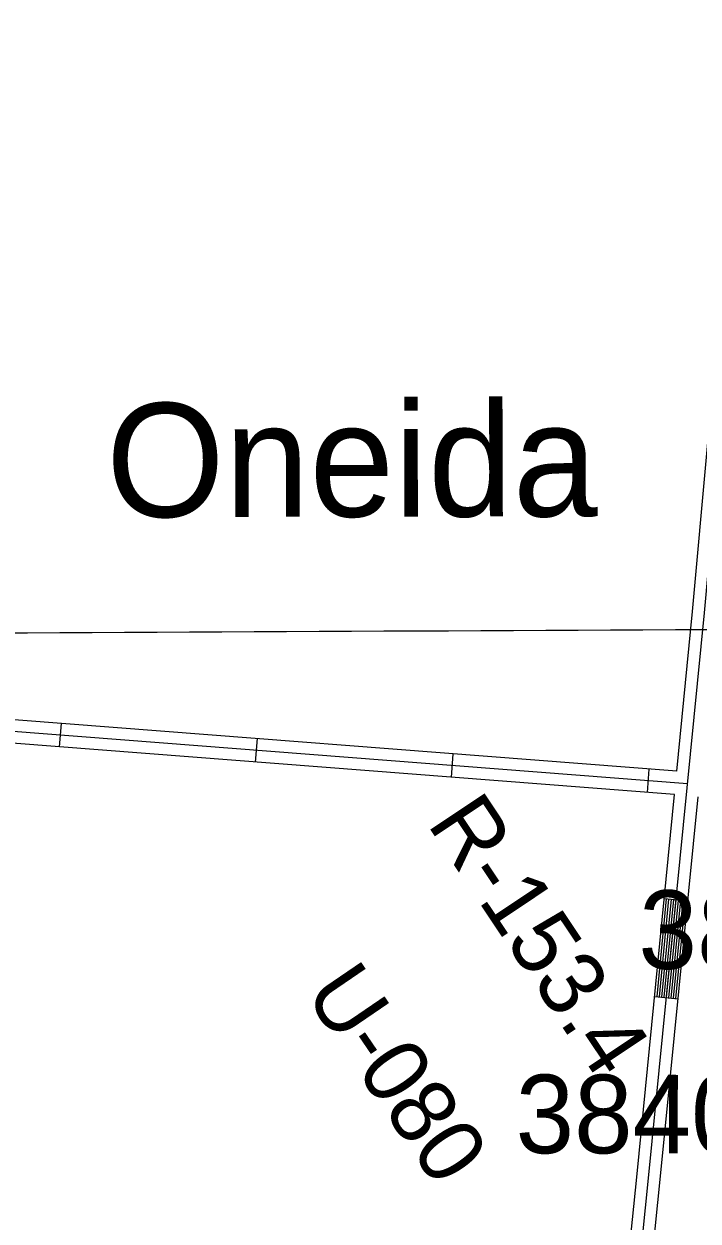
# Model space of a CAD drawing. Extents: x 3419139 to 3457078, y 540382 to 565875.
# Drawn here: x 3452584 to 3453441, y 551211 to 552735 of the extents above; entities that cross this region are included whole.
import ezdxf

# ---------------------------------------------------------------- set-up
doc = ezdxf.new("R2010")
doc.units = 0
for name, color, linetype in [('V-GRID-MAJR', 7, 'Continuous'), ('V-RIVR-RANG-IDEN', 7, 'Continuous'), ('V-ROAD-CNTR', 7, 'Continuous'), ('V-SURV-IDEN', 7, 'Continuous'), ('V-TOPO-GNAM-IDEN', 7, 'Continuous')]:
    doc.layers.add(name, color=color, linetype=linetype)

msp = doc.modelspace()

# ---------------------------------------------------------------- linework, layer by layer
at = {"layer": 'V-GRID-MAJR'}
msp.add_spline([(3423248.5, 551833.1), (3428523.1, 551854.2), (3433797.7, 551876), (3439072.3, 551898.7), (3444346.9, 551922.1), (3449621.5, 551946.2), (3454896.1, 551971.2)], degree=3, dxfattribs=at)
at = {"layer": 'V-ROAD-CNTR'}
for p, q in [((3452629.3, 551814.9), (3452631.6, 551844.8)), ((3452878.5, 551795.5), (3452880.9, 551825.4)), ((3453127.8, 551776.1), (3453130.1, 551806)), ((3453377, 551756.8), (3453379.4, 551786.7)), ((3453398.6, 551621.8), (3453428.4, 551618.8)), ((3453386.3, 551497.4), (3453416.1, 551494.4))]:
    msp.add_line(p, q, dxfattribs=at)
for points in [[(3453343.2, 550823.7), (3453344.4, 550930), (3453379, 551270.2), (3453449.5, 551985.5), (3453525.2, 552823.2), (3453567.1, 553344.9), (3453572.2, 553383.2), (3453581, 553413.4), (3453591.7, 553439.5), (3453616, 553481.4), (3453658.6, 553543.1), (3453688, 553594.5), (3453720.1, 553656.5), (3453724.1, 553674.2), (3453736, 553771.9), (3453793.6, 554410.9), (3453851.2, 555091.5), (3453909.6, 555747.5), (3453945.8, 556130), (3453974.9, 556467.7), (3454011.8, 556908.2), (3454080.8, 557648.6)], [(3453414.6, 551783.9), (3453434.6, 551987), (3453510.3, 552824.4), (3453552.2, 553346.5), (3453557.5, 553386.3), (3453566.9, 553418.3), (3453578.2, 553446.2), (3453603.3, 553489.5), (3453645.9, 553551.1), (3453674.9, 553601.7), (3453691.9, 553634.6)], [(3453414.6, 551783.9), (3452516.4, 551853.7), (3451811.9, 551908.2), (3451307.4, 551947.9), (3451008.7, 551971.6), (3451005.3, 551972.3), (3451001.2, 551973.2), (3450997.1, 551974.3), (3450992.9, 551975.3), (3450988.8, 551976.5), (3450984.7, 551977.7), (3450980.6, 551979), (3450976.6, 551980.3), (3450972.6, 551981.7), (3450968.6, 551983.2), (3450964.7, 551984.8), (3450960.8, 551986.4)], [(3453411.6, 551754.1), (3452514, 551823.8), (3451809.6, 551878.3), (3451305, 551918), (3451004.6, 551941.9), (3450999.1, 551943), (3450994.4, 551944), (3450989.8, 551945.1), (3450985.1, 551946.3), (3450980.5, 551947.6), (3450976, 551949), (3450971.4, 551950.4), (3450966.8, 551952), (3450962.3, 551953.6), (3450957.6, 551955.3)], [(3453428, 551767.8), (3452515.2, 551838.8), (3451810.7, 551893.2), (3451306.2, 551933), (3451006.7, 551956.7)], [(3453328.2, 550823.9), (3453329.4, 550930.9), (3453364, 551271.7), (3453411.6, 551754.1)], [(3453358.2, 550823.6), (3453359.4, 550929.2), (3453393.9, 551268.7), (3453441.5, 551751.2)], [(3453389.3, 551497.1), (3453401.5, 551621.5)], [(3453392.3, 551496.8), (3453404.5, 551621.2)], [(3453395.2, 551496.5), (3453407.5, 551620.9)], [(3453398.2, 551496.2), (3453410.5, 551620.6)], [(3453401.2, 551495.9), (3453413.5, 551620.3)], [(3453404.2, 551495.6), (3453416.5, 551620)], [(3453407.2, 551495.3), (3453419.5, 551619.7)], [(3453410.2, 551495), (3453422.4, 551619.4)], [(3453413.2, 551494.7), (3453425.4, 551619.1)]]:
    msp.add_lwpolyline(points, dxfattribs=at)

# ---------------------------------------------------------------- texts
at = {"layer": 'V-RIVR-RANG-IDEN'}
for s, rotation, p in [('R-153.4', 303.7342, (3453095.8, 551717.2)), ('U-080', 304.3105, (3452939.5, 551501.3))]:
    msp.add_text(s, height=83, rotation=rotation, dxfattribs=at).set_placement(p)
at = {"layer": 'V-SURV-IDEN'}
for s, rotation, p in [('3842+88.4', 358.9715, (3453365.2, 551533)), ('3840+18.0', 359.9301, (3453209.4, 551297.8))]:
    msp.add_text(s, height=100, rotation=rotation, dxfattribs=at).set_placement(p)
at = {"layer": 'V-TOPO-GNAM-IDEN'}
msp.add_text('Oneida', height=145, rotation=0.088, dxfattribs=at).set_placement((3452688.6, 552107.3))

doc.saveas('drawing.dxf')
